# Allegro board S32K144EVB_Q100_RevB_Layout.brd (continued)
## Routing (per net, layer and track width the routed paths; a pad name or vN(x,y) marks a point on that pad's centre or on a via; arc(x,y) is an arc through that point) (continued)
N20341806: length 99.1
  TOP w0.16: v1(88.69,13.75) R134.1 ; R135.1 v1(62.15,13.37)
  L3_MIX w0.16: v1(47.17,5.91) 47.17,6.91 44.54,9.55 44.54,16.39 46,17.85 46,25.48 48.37,27.85 48.37,47.91 45.68,50.6 J1.15
  BOTTOM w0.16: v1(47.17,5.91) 54.63,13.37 v1(62.15,13.37) 70.22,13.37 70.8,12.78 82.72,12.78 82.75,12.82 83.18,12.82 83.21,12.78 84.91,12.78 85.89,13.75 v1(88.69,13.75)
N20342136: length 49.8
  L3_MIX w0.16: v1(90.96,42.55) 90.96,40.44 88.84,38.32 88.84,16.99 90.21,15.62 90.21,14.08 89.89,13.76 v1(89.89,9.72)
  BOTTOM w0.16: v1(89.89,9.72) 89.11,9.72 87.67,8.28 81.25,8.28 79.44,6.47 79.44,5.86 J5.5 ; SH10.1 90.58,43.4 90.96,43.01 v1(90.96,42.55)
N20342745: length 54.9
  L3_MIX w0.16: v1(92.64,45.23) 92.64,45 93.57,44.07 93.57,15.28 92.72,14.43 92.72,10.69 90.04,8.01 84.13,8.01 J5.7
  BOTTOM w0.16: SH9.1 88.02,44.11 89.14,45.23 v1(92.64,45.23)
N20344624: length 54.8
  TOP w0.16: R144.1 R140.2 v1(80.66,44.89)
  L3_MIX w0.16: v1(82.32,8.82) 82.32,12.9 81.65,13.57 81.65,24.61 81.35,24.91 81.35,27.19 81.59,27.43 81.59,30.78 81.35,31.03 81.35,42.53 80.66,43.22 v1(80.66,44.89)
  BOTTOM w0.16: v1(82.32,8.82) 81.08,8.82 79.06,6.8 70.23,6.8 J4.15
N20344681: length 53.3
  TOP w0.16: v1(76.89,44.89) R141.2 R145.1
  L3_MIX w0.16: v1(76.82,7.89) 76.82,9.82 76.39,10.25 76.39,13.75 76.68,14.05 76.68,32.37 77.62,33.31 77.62,42.44 76.89,43.17 v1(76.89,44.89)
  BOTTOM w0.16: v1(76.82,7.89) 67.45,7.89 66,6.44 J4.13
N20344687: length 21.8
  TOP w0.16: v1(74.81,13.25) 76.12,13.25 76.38,13.5 R142.2 R146.1
  L3_MIX w0.16: v1(74.81,13.25) v1(74.81,8.85)
  BOTTOM w0.16: v1(74.81,8.85) 66.19,8.85 64.2,6.86 64.2,5.86 J4.11
N20344693: length 49.2
  TOP w0.16: v1(90.6,21.46) R143.2 88.69,22.24 R147.1
  L3_MIX w0.16: v1(90.6,21.46) 90.6,18.49 91.86,17.23 v1(91.86,11.44)
  BOTTOM w0.16: v1(91.86,11.44) 64.72,11.44 63.53,10.25 63.53,8.77 60.92,6.16 J4.9
N20362140: length 3.4
  TOP w0.16: R93.2 42.37,19.57 U19.24
N20408163: length 3.4
  TOP w0.381: R169.2 R170.2 U15.3
N20408770: length 1.6
  TOP w0.254: U15.4 C59.1
N20435841: length 47.5
  TOP w0.16: J4.7 58.38,6.16 59.71,7.49 64.81,7.49 68.07,10.74 74.26,10.74 75.66,9.34 77.92,9.34 79.12,10.55 88.65,10.55 92.81,14.7 v1(92.81,17.82)
  BOTTOM w0.16: v1(92.81,17.82) 89.34,17.82 88.85,18.31 SH4.2
N20435866: length 49.7
  TOP w0.16: J4.5 55.84,6.17 58.56,8.89 64.12,8.89 66.93,11.7 74.6,11.7 76.18,10.12 77.62,10.12 78.86,11.36 84.76,11.36 86.18,12.78 89.79,12.78 92.14,15.13 v1(92.14,18.48)
  BOTTOM w0.16: v1(92.14,18.48) 90.77,18.48 89.46,19.79 SH5.2
N20437402: length 63.4
  L3_MIX w0.16: J1.3 59.29,51.75 v1(59.29,29.79)
  BOTTOM w0.16: SH12.2 94.34,28.54 92.45,30.43 90.91,30.43 90.73,30.62 77.7,30.62 77.22,30.14 71.08,30.14 70.73,29.79 v1(59.29,29.79)
N20437406: length 55.8
  L3_MIX w0.16: v1(62.14,26.25) 62.14,50.48 63.46,51.8 J1.1
  BOTTOM w0.16: SH11.2 88.15,28.54 87.41,27.8 80.43,27.8 79.21,26.58 72.73,26.58 72.4,26.25 v1(62.14,26.25)
N20438625: length 69.9
  TOP w0.16: v1(64.17,9.96) 61,9.96 60.44,9.4 56.54,9.4 53.3,6.16 J4.3
  L3_MIX w0.16: v1(90.66,10.28) 90.66,12.02 91.42,12.78 91.42,16.79 89.97,18.24 89.97,35.97 90.88,36.88 v1(90.88,36.96)
  BOTTOM w0.16: SH15.2 v1(90.88,36.96) ; v1(90.66,10.28) 87.78,10.28 87.15,10.91 78.18,10.91 77.72,10.45 65.67,10.45 65.19,9.96 v1(64.17,9.96)
N20438629: length 73.1
  TOP w0.16: J4.1 50.76,6.92 54.57,10.73 64.24,10.73 65.65,12.14 74.9,12.14 76.56,10.48 77.44,10.48 78.74,11.78 84.01,11.78 85.52,13.29 89.42,13.29 90.93,14.8 v1(90.93,15.65)
  L3_MIX w0.16: v1(90.93,38.63) 89.37,37.07 89.37,17.69 90.93,16.13 v1(90.93,15.65)
  BOTTOM w0.16: SH14.2 v1(90.93,38.63)

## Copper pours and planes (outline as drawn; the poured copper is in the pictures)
GND on TOP: 20.65,36.02 21.01,36.38 22.41,36.38 25.21,33.58 25.21,32.5 24.53,31.83 23.5,31.83 20.65,34.68
GND on BOTTOM: 106.17,8.89 103.72,2.98 97.82,0.53 8.92,0.53 3.01,2.98 0.56,8.89 0.53,49.53 2.98,55.44 8.89,57.89 97.82,57.89 103.72,55.44 106.17,49.53 ; 40 cut-outs
GND on L2_GND: 106.17,8.89 103.72,2.98 97.82,0.53 8.92,0.53 3.01,2.98 0.56,8.89 0.53,49.53 2.98,55.44 8.89,57.89 97.82,57.89 103.72,55.44 106.17,49.53
GND on L3_MIX: 106.17,8.89 103.72,2.98 97.82,0.53 8.92,0.53 3.01,2.98 0.56,8.89 0.53,49.53 2.98,55.44 8.89,57.89 97.82,57.89 103.72,55.44 106.17,49.53 ; 67 cut-outs
P3V3 on TOP: 40.63,27.32 48.16,27.32 48.52,27.68 48.52,31.09 47.27,32.34 42.53,32.34 42.53,34.95 48.35,34.95 48.35,33.87 50.33,31.89 52.95,31.89 52.95,25.74 51.99,24.78 47.07,24.78 46.74,25.12 40.63,25.12
P3V3 on L3_MIX: 39.4,27.31 41.21,27.31 41.21,25.29 39.98,24.05 39.98,10.16 36.8,6.99 36.8,4.79 33.96,4.79 33.96,8.28 37.76,12.09 37.76,25.68
P3V3_SDA on TOP: 31.33,37.21 31.33,35.49 31.24,35.39 29.19,35.39 29.01,35.58 29.01,37.25 31.29,37.25
P3V3_SDA on TOP: 8.44,51.41 9.73,51.41 10.09,51.05 10.09,49.5 9.33,49.5 8.44,50.4
P3V3_SDA on BOTTOM: 29.6,36.74 29.6,37.88 30.45,38.74 33.13,38.74 34.22,39.82 34.22,40.4 35.4,41.58 37.86,41.58 37.86,42.89 34.29,42.89 31.36,39.96 28.92,39.96 28.87,40 28.87,42.35 31.09,42.35 31.38,42.64 31.38,43.4 30.42,44.36 30.42,44.43 30.44,44.44 30.44,45.69 29.03,45.69 26.89,47.83 22.35,47.83 18.16,52.02 7.52,52.02 6.75,52.79 4.78,52.79 4.72,52.73 4.72,51.49 5.95,50.25 9.39,50.25 10.59,49.05 10.59,27.64 11.78,26.45 18.7,26.45 19.42,27.16 19.42,28.39 14.57,28.39 14.57,33.88 16.92,36.23 16.92,38.23 16.44,38.23 16.27,38.06 16.27,36.67 13.58,33.98 13.58,31.39 12.24,31.39 11.86,31.77 11.86,35.72 13.48,37.34 13.48,43.84 14.48,44.84 16.84,44.84 19.22,42.46 19.85,43.08 19.85,44.32 17.24,46.93 17.24,48.9 19.44,48.9 21.68,46.66 24.62,46.66 26.22,45.07 28.25,45.07 28.25,42.82 27.57,42.13 27.57,40.1 27.09,39.62 27.09,38.53 27.28,38.34 28.05,38.34 28.3,38.09 28.3,37.32 28.88,36.74
P5V0 on TOP: 39.06,33.58 40.62,32.02 47.09,32.02 48.21,30.9 48.21,29.97 44.86,29.97 43.98,29.09 38.74,29.09 37.42,30.4 37.42,36.48 39.06,36.48
P5V0 on BOTTOM: 30.4,34.64 39.24,34.64 39.98,33.89 39.98,30.26 39.26,29.54 29.84,29.54 29.52,29.86 29.52,33.75
P5V0 on L3_MIX: 37.37,4.82 37.37,6.2 41.46,10.29 41.46,30.39 42.73,31.66 43.44,31.66 43.44,8.43 39.82,4.82
P5V_SDA on TOP: 22.29,44.5 23.47,45.69 22.26,46.9 6.97,46.9 6.97,45.62 17.57,45.62 17.93,45.99 19.59,45.99 19.95,45.62 21.17,45.62
P5V_SDA on BOTTOM: 6.91,45.99 6.91,28.58 9.61,28.58 9.61,46.33 7.24,46.33
VBATT on TOP: 21.55,12.28 26.92,12.28 27.14,12.06 27.14,7.11 26.69,6.67 22.08,6.67 21.55,7.2
VDD on TOP: 103.84,7.96 103.08,8.72 103.08,14.6 103.95,15.47 104.95,15.47 104.95,7.97 104.94,7.96
VDD on TOP: 39.81,38.45 51.32,38.45 52.51,39.64 54.85,39.64 54.85,38.09 54.84,38.08 54.84,35.2 42.32,35.2 42.32,33.41 40.12,33.41 39.81,33.73
VDD on BOTTOM: 69.52,3.93 90.42,3.93 102.7,16.22 102.7,39.11 99.48,42.33 99.48,46.47 94.18,46.47 89.52,51.12 79.96,51.12 79.96,57.68 98.72,57.68 104.69,51.7 104.69,40.06 105.43,39.32 105.43,30.21 105.7,29.94 105.7,28.81 105.43,28.54 105.43,19.25 104.68,18.5 104.68,6.92 98.33,0.56 47.54,0.56 47.54,1.22 69.36,1.22 69.46,1.33 69.46,3.88
VDD on L3_MIX: 71.9,3.86 71.9,0.56 26.38,0.56 25.9,1.05 25.9,8.08 32.93,15.11 32.93,28.9 42.51,38.48 44.1,38.48 44.1,33.88 36.62,26.41 36.62,13.54 35.74,12.66 35.74,11.23 32.06,7.55 32.06,3.86
VDD_MCU on TOP: 58.07,41.96 58.07,34.46 56.85,34.46 56.85,32.09 62.99,32.09 65.08,30 68.83,30 69.15,29.68 75.6,29.68 75.6,31.21 69.22,31.21 68.82,30.81 65.75,30.81 64.6,31.97 64.6,33.35 61.36,33.35 59.92,34.78 59.92,41.96
VDD_MCU on L3_MIX: 75.31,40.88 75.31,34.93 74.55,34.18 74.55,19.62 74.88,19.3 74.88,17.74 75.8,17.74 75.8,22.26 75.6,22.46 75.6,33.29 76.25,33.94 76.25,40.88
SBC_VB on TOP: 29.26,24.59 32.19,24.59 33.95,26.35 33.95,28.16 31.57,28.16 29.26,25.84
SBC_VDD on TOP: 40.17,23.04 38.39,23.04 37.7,23.73 37.2,23.73 35.11,25.82 35.11,28.72 36.9,28.72 36.9,36.34 32.86,36.34 32.86,32.41 30.57,32.41 30.57,28.62 34.41,28.62 34.41,24.09 35.9,22.6 40.17,22.6
SBC_VE on TOP: 35.59,28.13 38.03,28.13 40.31,25.85 40.31,24.56 37.4,24.56 35.59,26.37
SDA_USBSHIELD on TOP (solid shape): 2.43,48.27 5.1,48.27 5.1,46.25 3.86,46.25 3.86,47.25 0.53,47.25 0.53,48.98 2.43,48.98
SDA_USBSHIELD on TOP (solid shape): 5.1,39.78 2.43,39.78 2.43,39.07 0.53,39.07 0.53,40.8 3.86,40.8 3.86,41.8 5.1,41.8
SDA_USBSHIELD on TOP: 5.01,39.78 6.6,39.78 6.6,40.84 6.59,40.85 4.97,40.85 4.93,40.81 4.93,39.86
V_TGTMCU on TOP: 0.83,51.31 3.57,51.31 3.77,51.11 3.77,49.76 3.45,49.43 1.64,49.43 0.83,50.24
V_TGTMCU on L3_MIX: 1.3,51.32 7.24,51.32 9.03,49.52 9.03,47.25 9.97,46.32 12.11,46.32 15.42,49.62 32.42,49.62 35.79,46.26 39.87,46.26 39.87,42.24 38.09,42.24 38.09,43.84 34.98,43.84 30.96,47.86 29.93,47.86 29.93,46.9 31.22,45.61 31.22,41.9 30.35,41.04 30.35,38.27 28.8,38.27 28.8,45.71 27.13,47.39 15.51,47.39 13.28,45.15 8.99,45.15 4.85,49.29 1.3,49.29
VSUP on TOP: 28.15,14.56 31.85,14.56 32.24,14.94 38.11,14.94 38.39,14.66 41.62,14.66 41.62,10.32 44.17,10.32 44.17,7.68 39.7,7.68 39.7,12.68 34.11,12.68 34.11,10.31 27.59,10.31 27.59,14
VSUP on BOTTOM: 28.28,24.55 31.6,24.55 32.15,24 32.15,13.97 31.84,13.66 30.09,13.66 30.05,13.7 30.05,14.39 30.7,15.05 30.7,22.88 30.2,23.38 28.28,23.38

Small or netless copper shapes (teardrops, artwork), in the pictures only: 1 on TOP

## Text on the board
BOTTOM: 170-28810 REV B | 7 OF 10 | SECONDARY SIDE
Board Geometry/Soldermask Bottom: 8 OF 10 | SECONDARY SOLDERMASK
Ref Des/Silkscreen Bottom: GND | LIN | VBAT | CAN_HI | CAN_LO | VDD | NC | E0 | E1 | AREF | A14 | E7 | C13 | B2 | B3 | C12 | B4 | E8 | B5 | D0 | D14 | B6 | VIN | D16 | D13 | B7 | D15 | E10 | RESET | 3.3V | E9 | 5V | C5 | C4 | A10 | A4 | C11 | E3 | D4 | C7 | C10 | D3 | B12 | C6 | B11 | D5 | B0 | B17 | B10 | D12 | B1 | B14 | B9 | D11 | A6 | B15 | D10 | B8 | C0 | B16 | A3 | A17 | E2 | C14 | A11 | A2 | E6 | C3 | E4 | A9 | A8 | E5 | E12 | A12 | E16 | A15 | A13 | D17 | E15 | A16 | C9 | E14 | A1 | C8 | E13 | A0 | C16 | D8 | A7 | C17 | D9 | B13 | D2 | E11 | C1 | D1 | D7 | C2 | D6 | C15 | SAFE | SBC | SCH | 700 | OpenSDA | 9 OF 10 | SECONDARY SILKSCREEN
User.Comments: 1 OF 1 | TEST PROBE | 1/1 | 1
TOP: 4 OF 10 | PRIMARY SIDE
Board Geometry/Soldermask Top: 3 OF 10 | PRIMARY SOLDERMASK
Ref Des/Silkscreen Top: SBC_IO | VSUP | LIN | GND | RESET | SBC_VDD | P5V0 | VDD | SWD_CLK | SWD_DIO | P3V3 | B | G | R | CAN | LO | HI | SDA | PWR IN (5-12V) | MCU | SWD | POT | TOUCH TWR-PI | 2 OF 10 | PRIMARY SILKSCREEN | FRDMPK144-Q100
L2_GND: 5 OF 10 | GROUND PLANE
L3_MIX: 6 OF 10 | MIXED SIGNAL
DIMENSION: PRIMARY DATUM | GRID ORIGIN
BODY_CENTER: 22. | INTENTIONAL SHORT ON: | Location           RefDes      Net 1                     Net 2 | (113.50 1329.90)   J9        P3V3_SDA               &  SDA_VOUT33 | (299.72 1681.10)   J105      SDA_RST_TGTMCU_J_B     &  SDA_RST_TGTMCU_B | (1213.10 1300.30)  SH1       V_TGTMCU               &  VDD | (1278.70 1578.40)  J8        SWD_CLK_TGTMCU_BUF     &  JTAG_TCLK/SWD_CLK | (1278.70 1442.70)  J106      SWD_DIO_TGTMCU_BUF     &  JTAG_TMS/SWD_DIO_PTA4 | (3114.40 519.40)   SH4       PTB1                   &  N20435841 | (3114.40 577.60)   SH5       PTB0                   &  N20435866 | (3199.40 862.83)   SH13      N20340793              &  PTD2 | (3199.40 922.00)   SH11      PTA2                   &  N20437406 | (3146.70 1319.30)  SH14      PTD4                   &  N20438629 | (3146.70 1253.80)  SH15      PTB12                  &  N20438625 | (3116.66 1475.88)  SH9       N20342745              &  PTA0 | (3181.49 1475.53)  SH10      N20342136              &  PTA1 | (3511.10 922.00)   SH12      PTA3                   &  N20437402 | (3619.50 790.40)   SH16      N20340042              &  PTB13 | (3619.50 1053.50)  SH8       N20340033              &  PTA7 | 16 | 17 | 8
PASTEMASK_TOP: 1 OF 10 | PASTEMASK TOP
User.5: 10 OF 10 | SECONDARY PASTEMASK
User.14: 07-24-15 | O.R. | B | RE-SPIN PER ECO58831
User.20: FIGURE | SIZE | 8.0 | 10.0 | 14.0 | 28.0 | 40.0 | 53.0 | 100.0 | 125.0 | 34.0x26.0 | 60.0x33.0 | 111.0x32.0 | 122.0x32.0 | DRILL CHART: TOP to BOTTOM | ALL UNITS ARE IN MILS | TOLERANCE | +0.0/-8.0 | +0.0/-10.0 | +2.0/-2.0 | +3.0/-3.0 | +3.0/-0.0 | PLATED | NON-PLATED | QTY | 352 | 461 | 24 | 22 | 144 | 2 | 1 | 4 | 3
